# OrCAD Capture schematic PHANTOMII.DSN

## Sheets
1 PhantomII System: size C; title: Phantom ROV: System
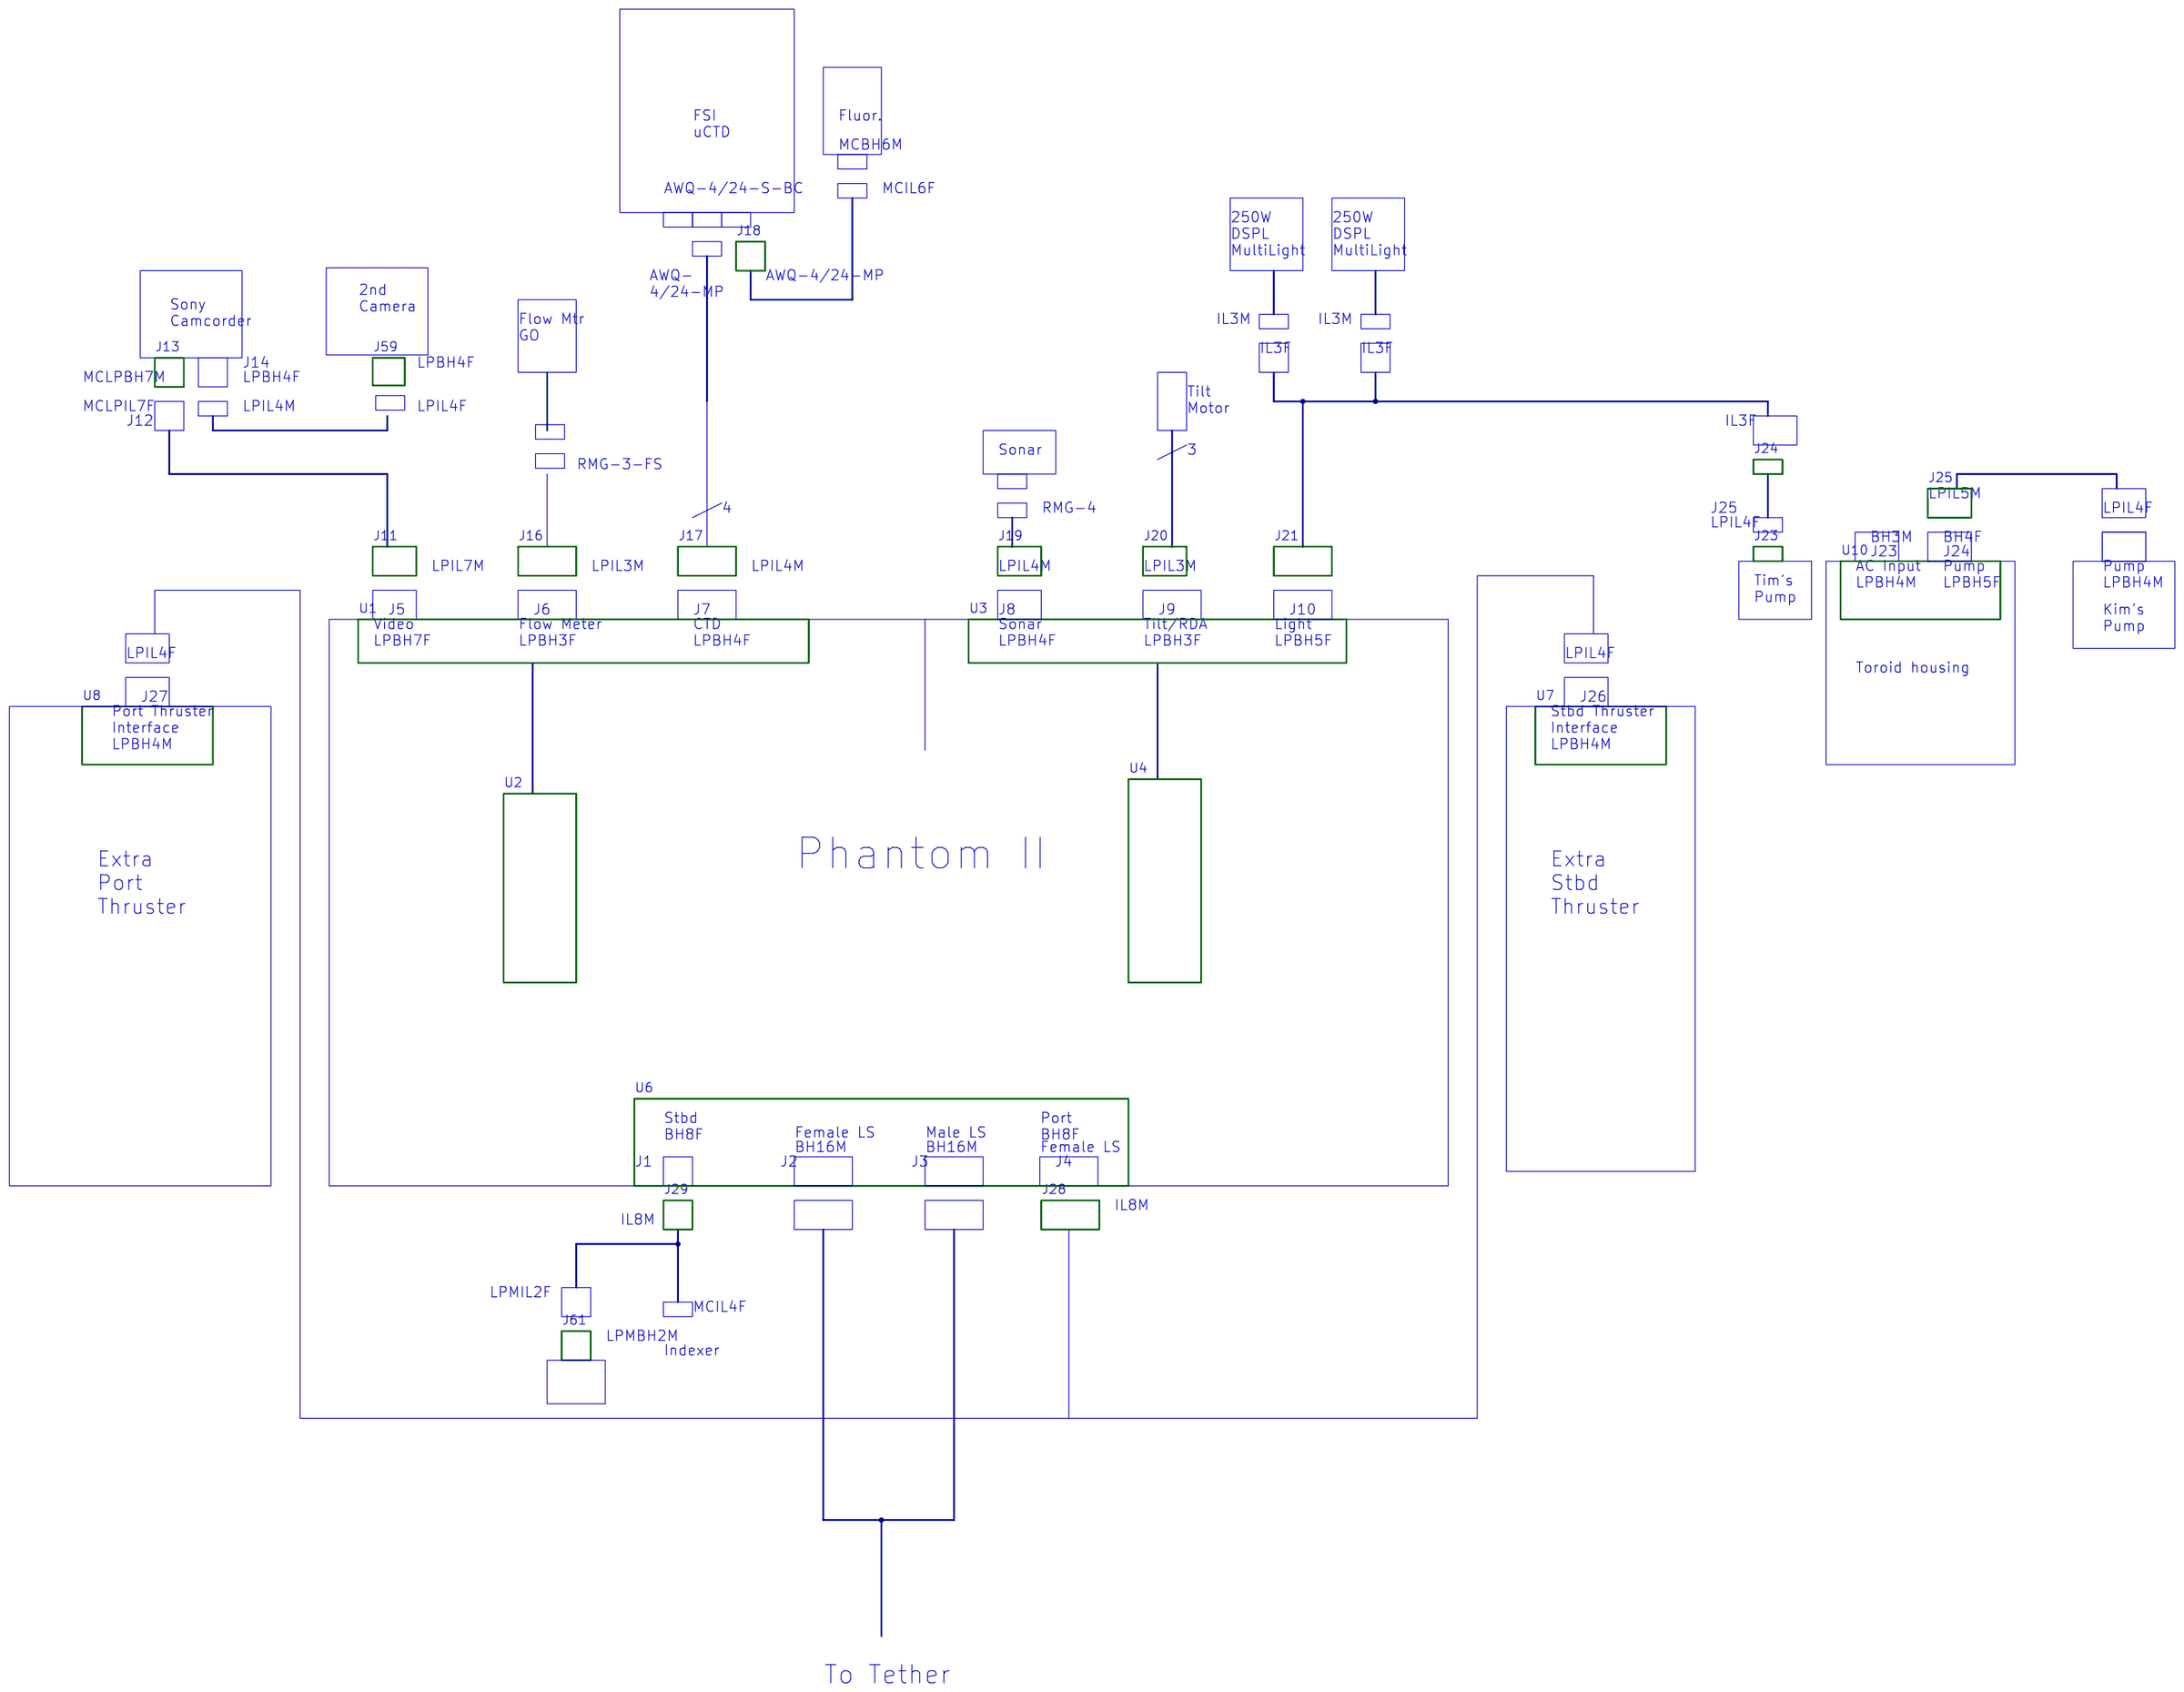
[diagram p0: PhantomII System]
2 J28: size A; title: J28: Phantom Spare Thrusters Cable; block J28
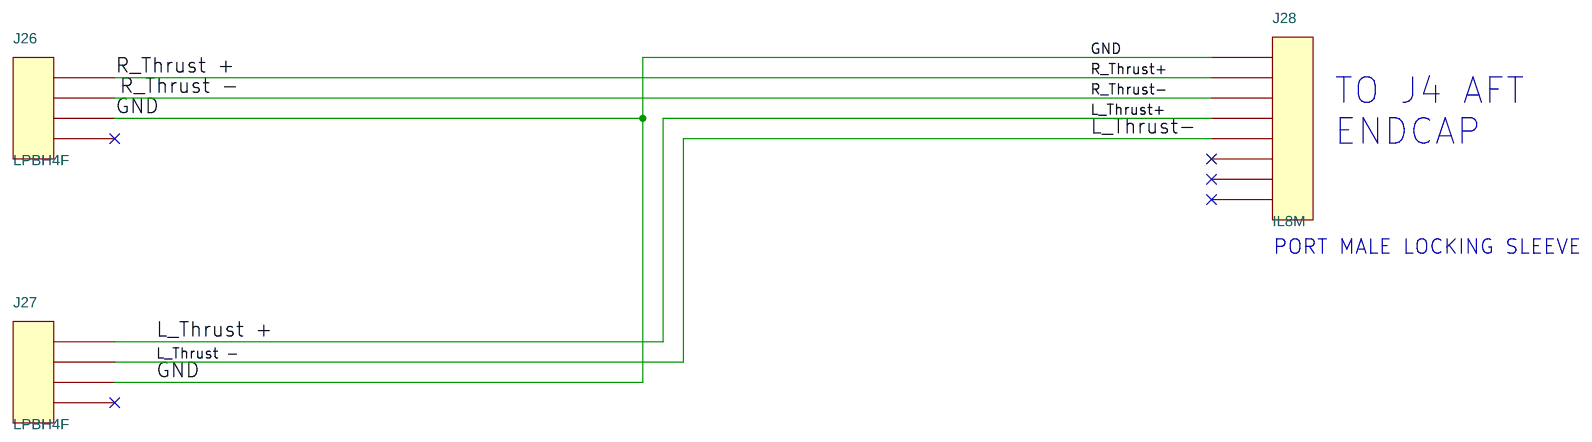
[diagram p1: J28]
3 J24: size A; title: J24: Tim's Pump Cable; block J24
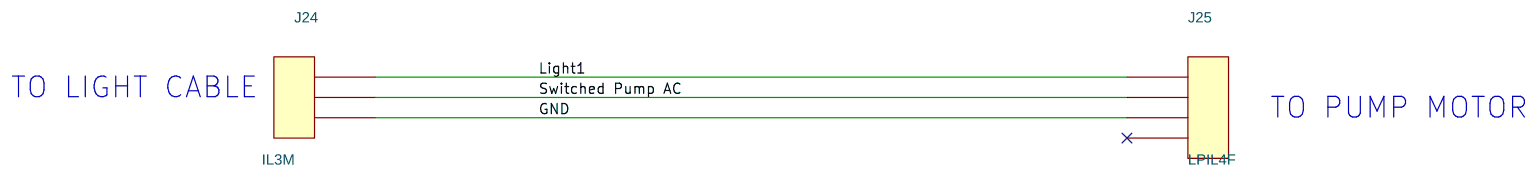
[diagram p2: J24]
4 J25: size A; title: J25: Phantom Pump Cable; block J25
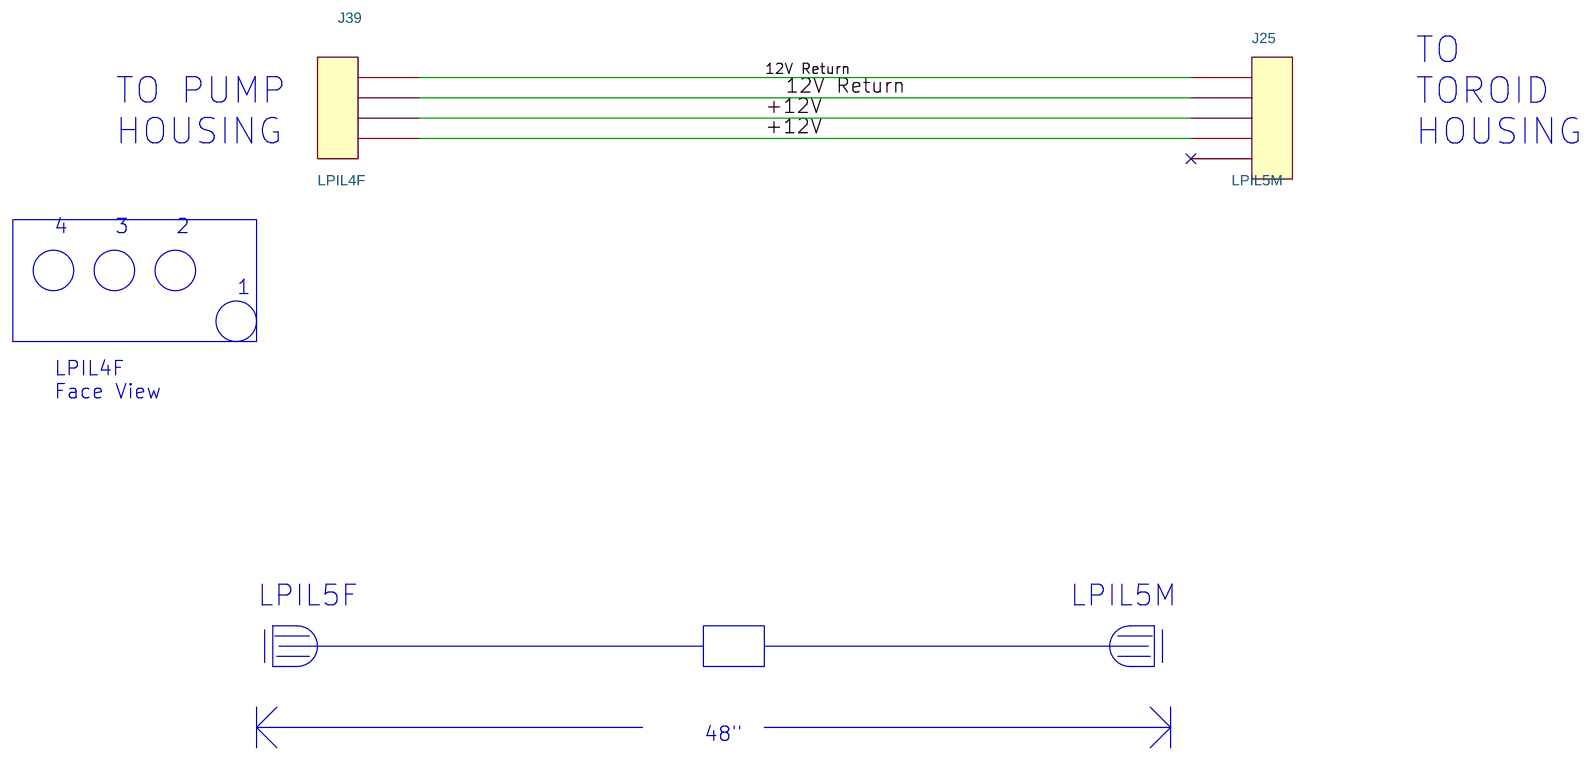
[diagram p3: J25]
5 J29: size A; title: J29:Indexer Cable; block J29
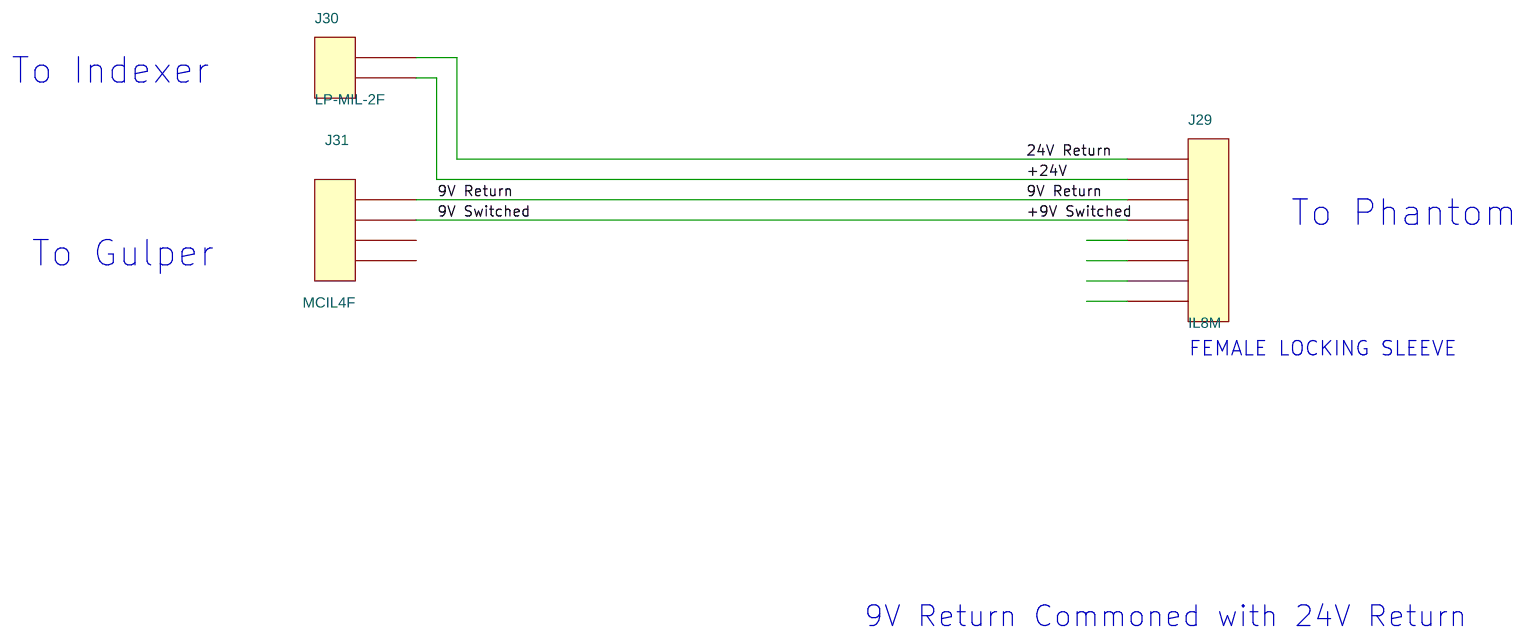
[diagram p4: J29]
6 J11: size A; title: Phantom: J11 Video Cable; block J11
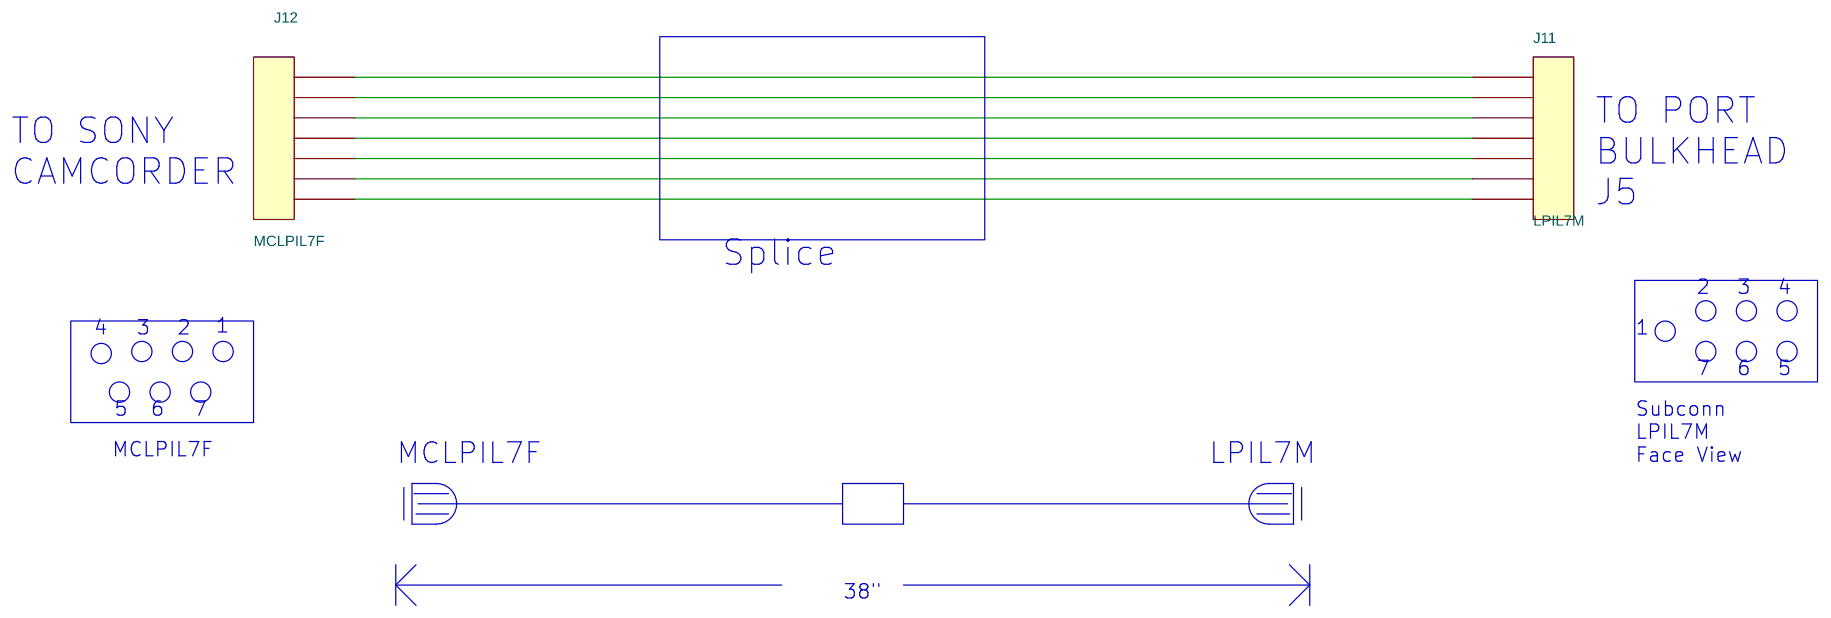
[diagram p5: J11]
7 J13: size B; title: J13: Camcorder Housing Internal Wiring; rev: 1.1.0; block J13
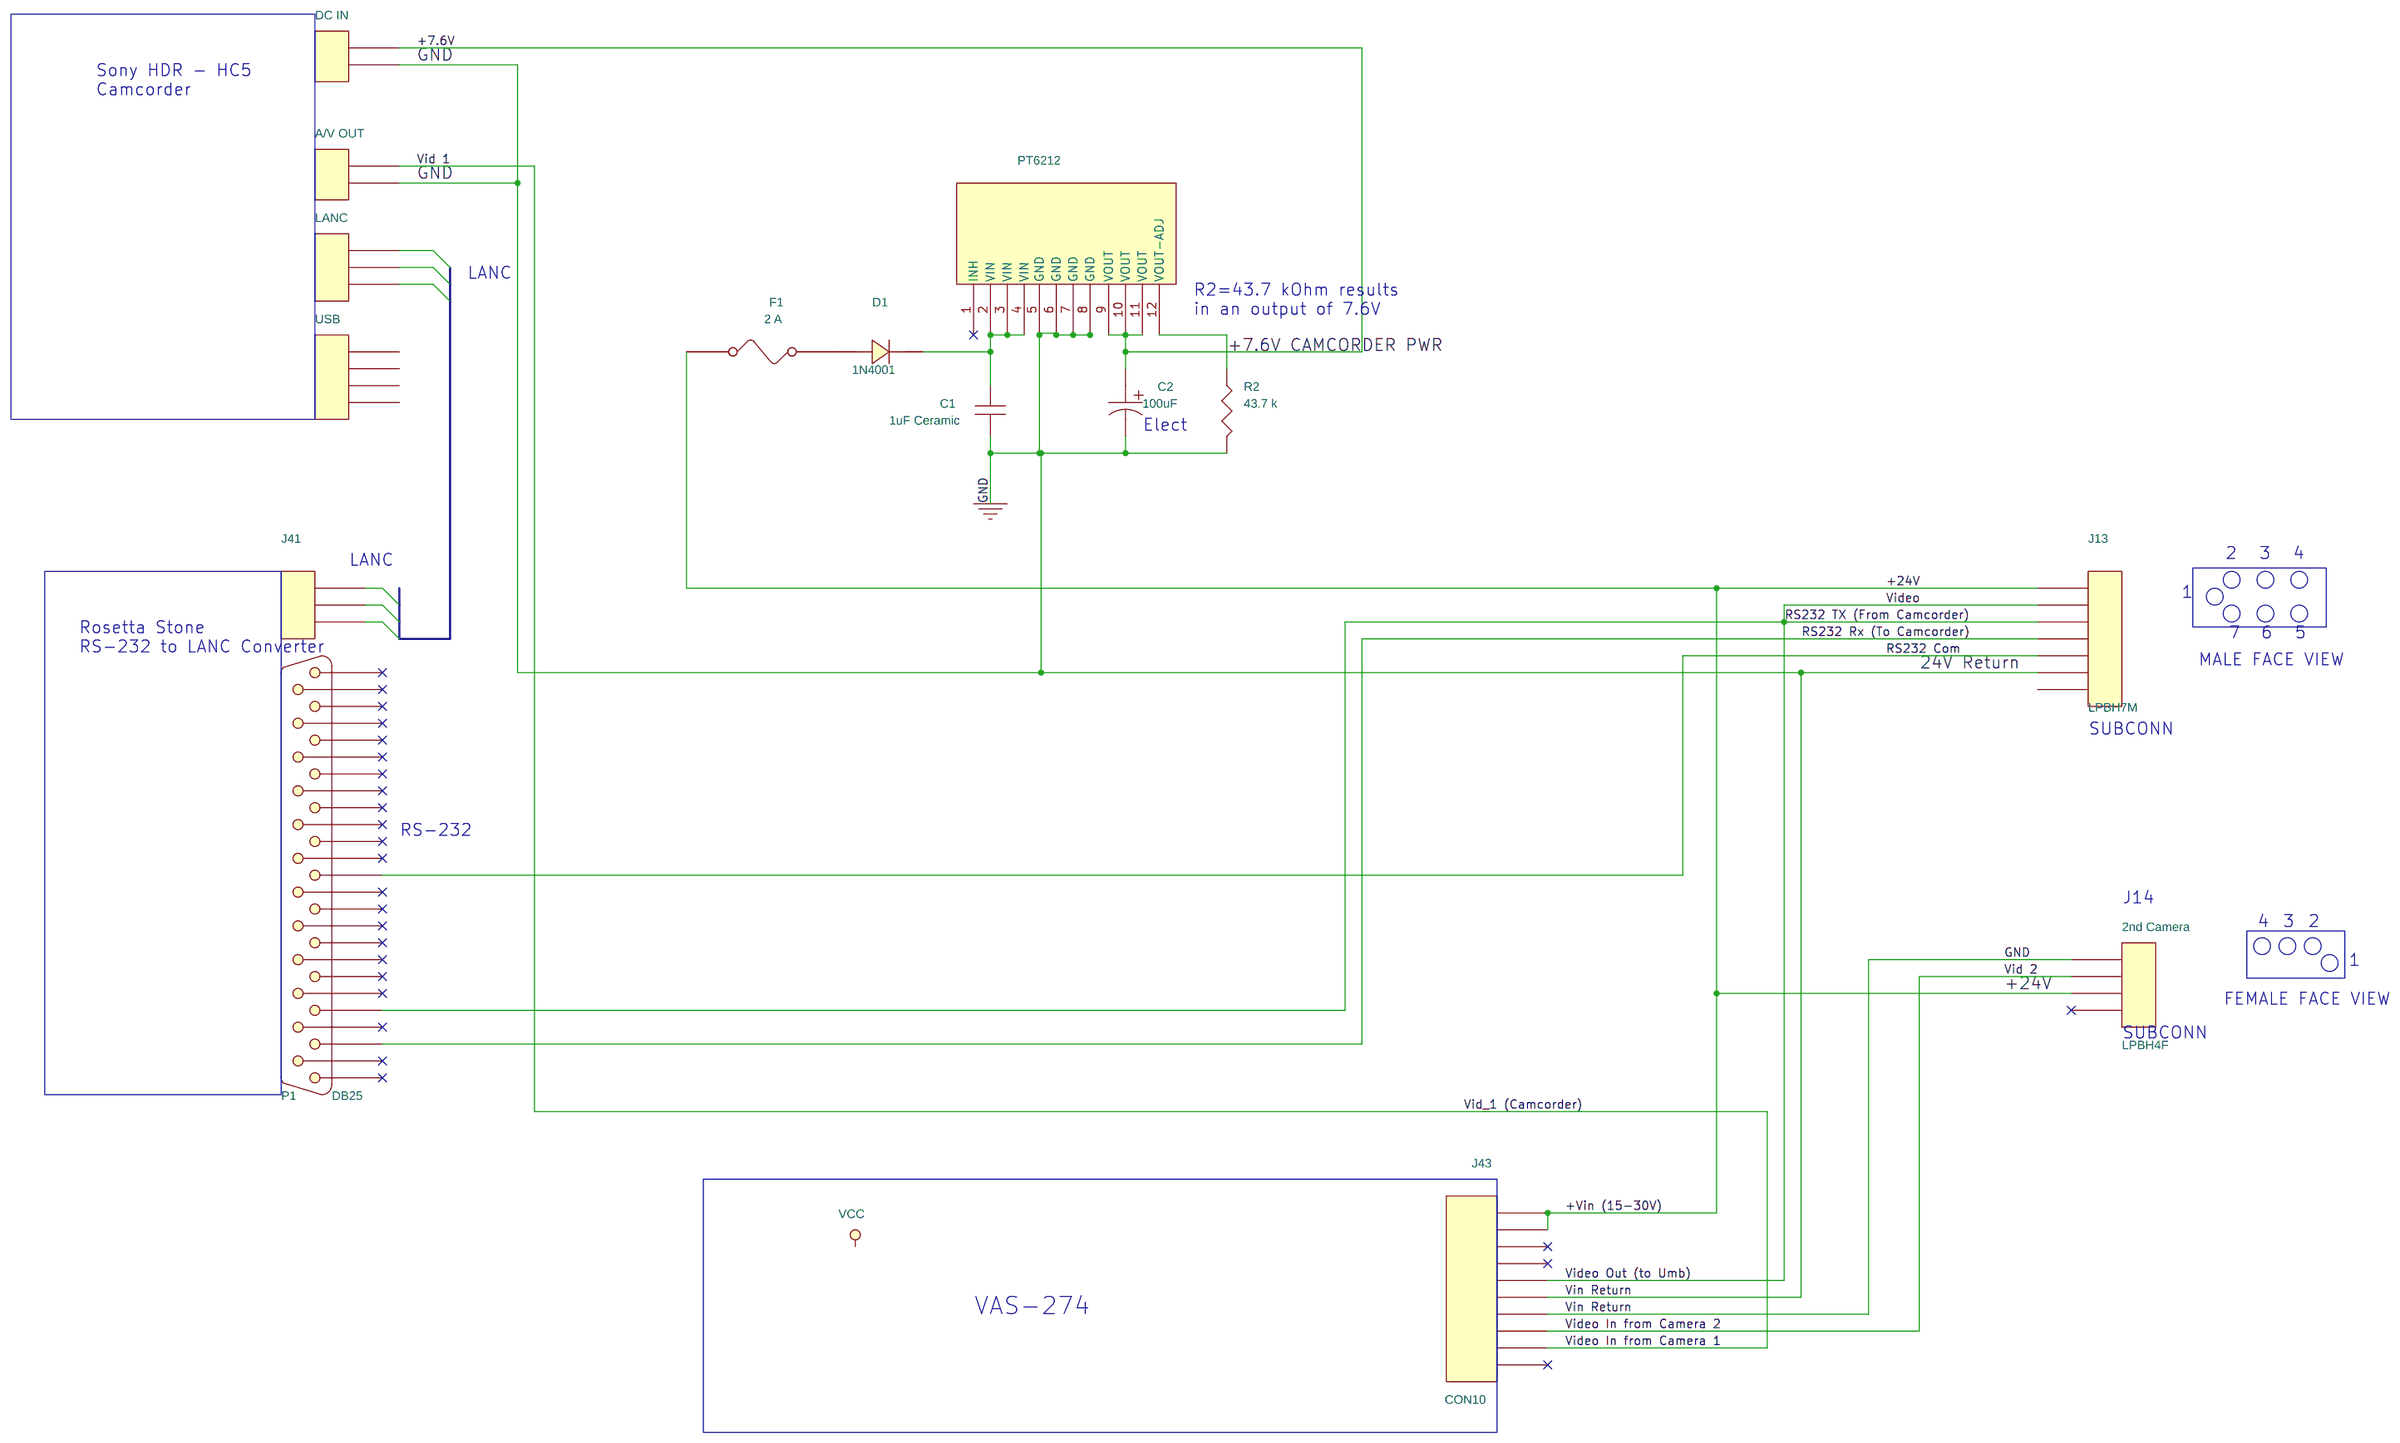
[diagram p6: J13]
8 J15: title: J15: SIT Camera Wiring
9 J21: size A; title: J21: Lights and Pump Cable; block J21
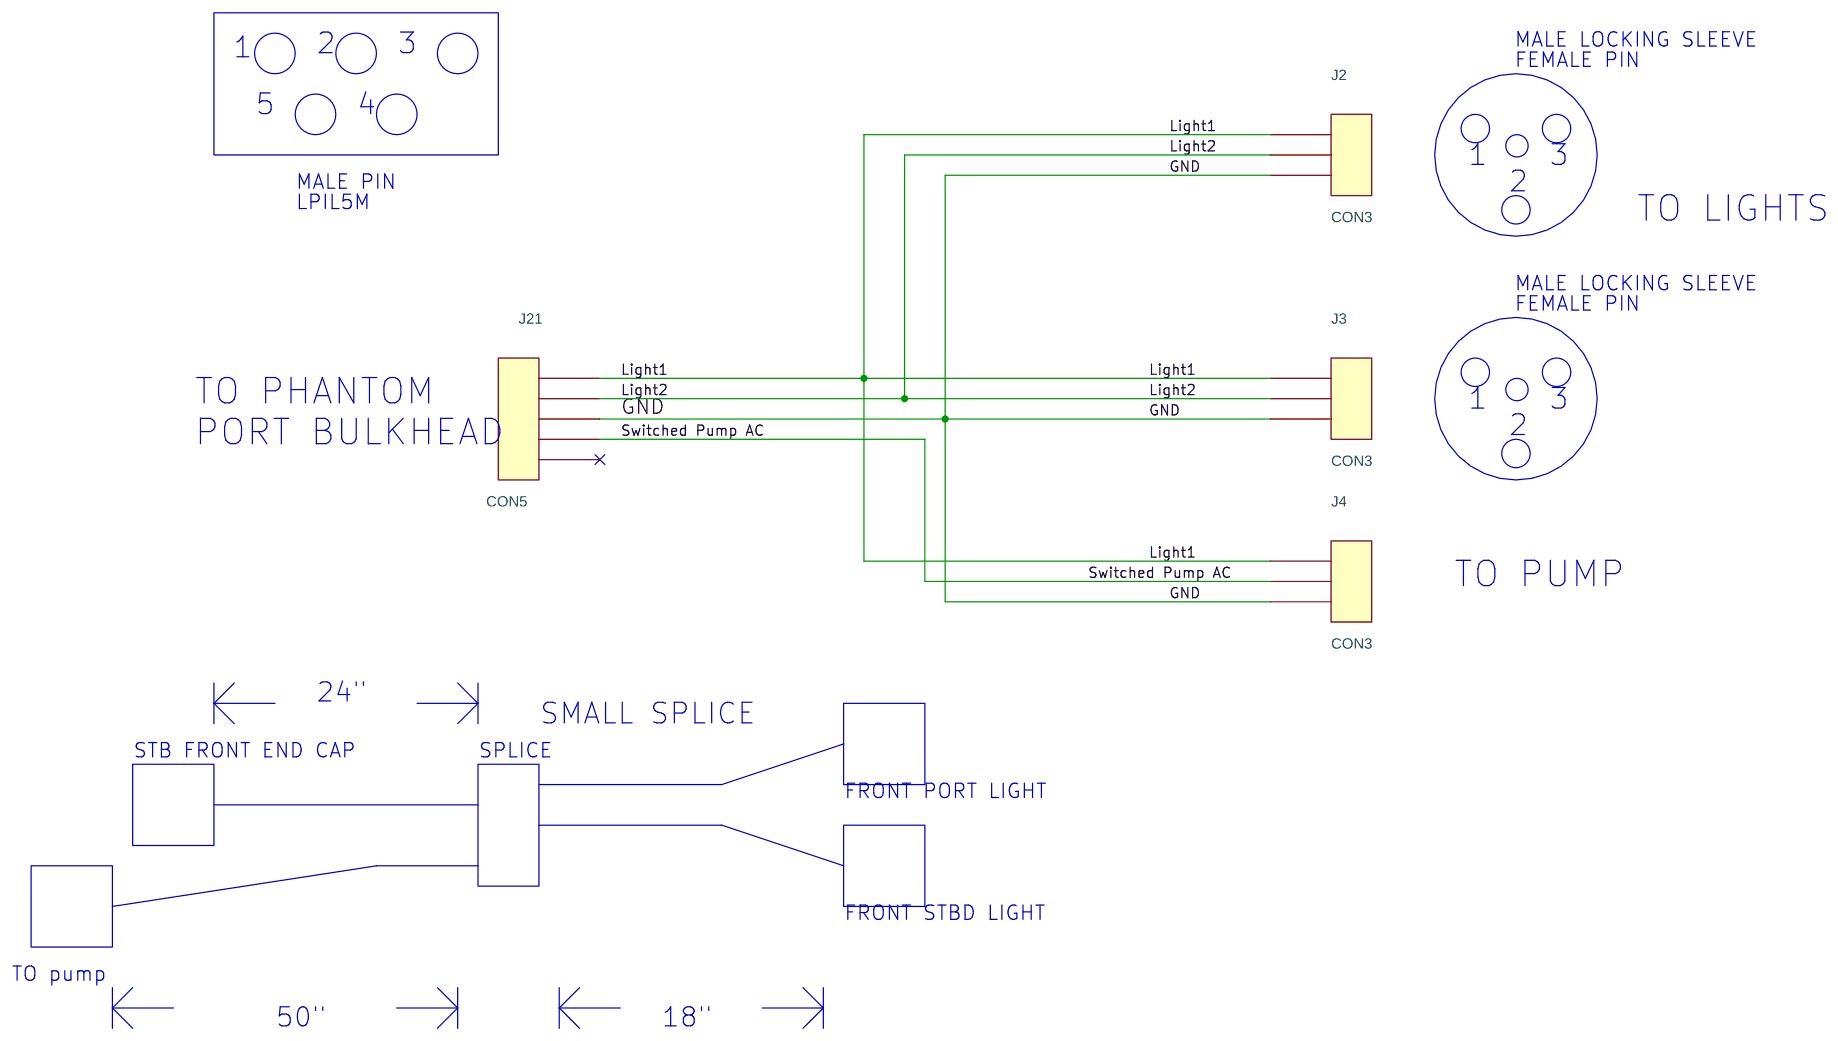
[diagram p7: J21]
10 J19: size A; title: Phantom II: J19 Sonar Cable; block J19
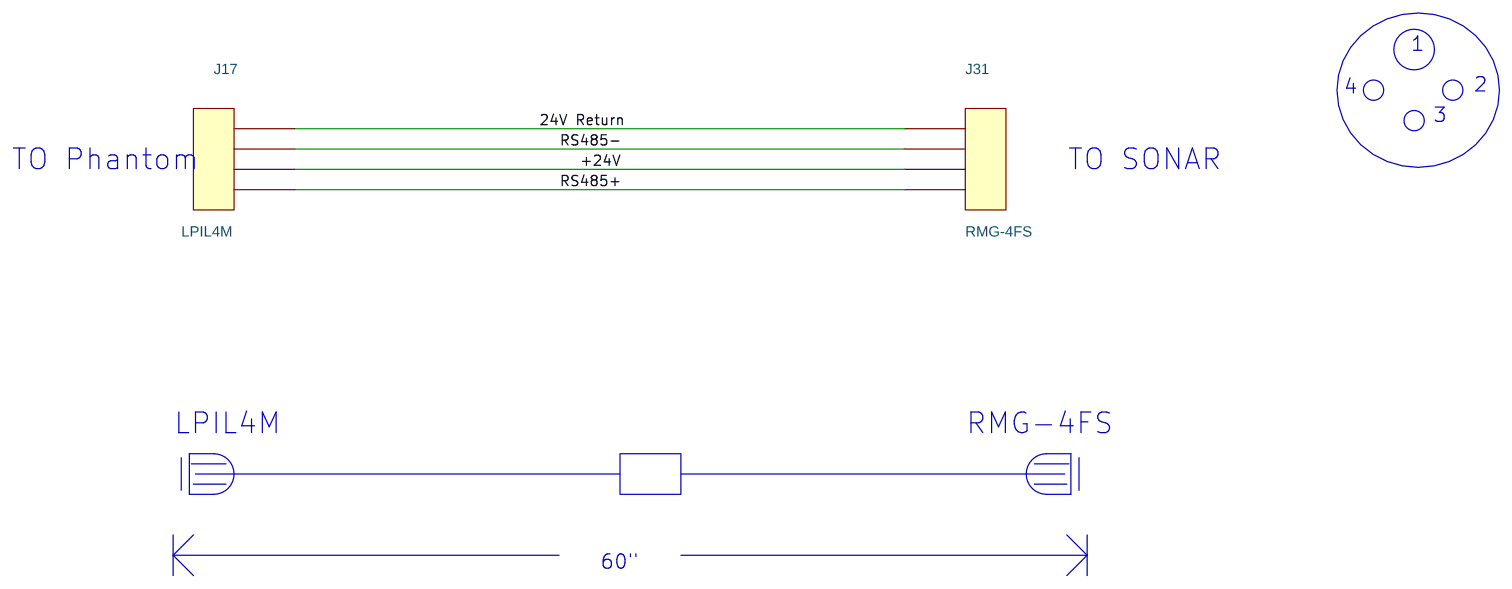
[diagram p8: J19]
11 J18: size A; title: J18: Phantom Fluorometer Cable; block J18
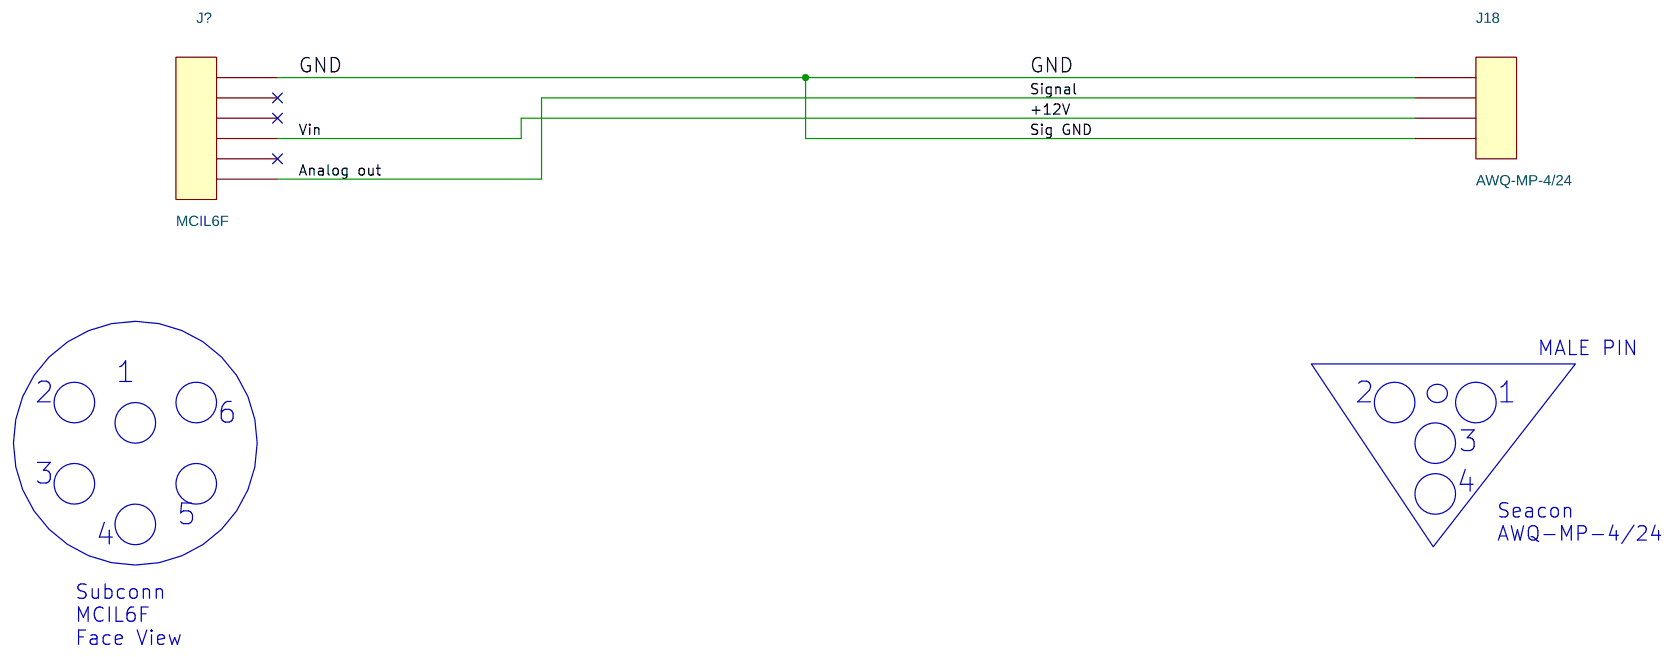
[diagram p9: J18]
12 J23: size A; title: J23: Tim's Pump Motor; block J23
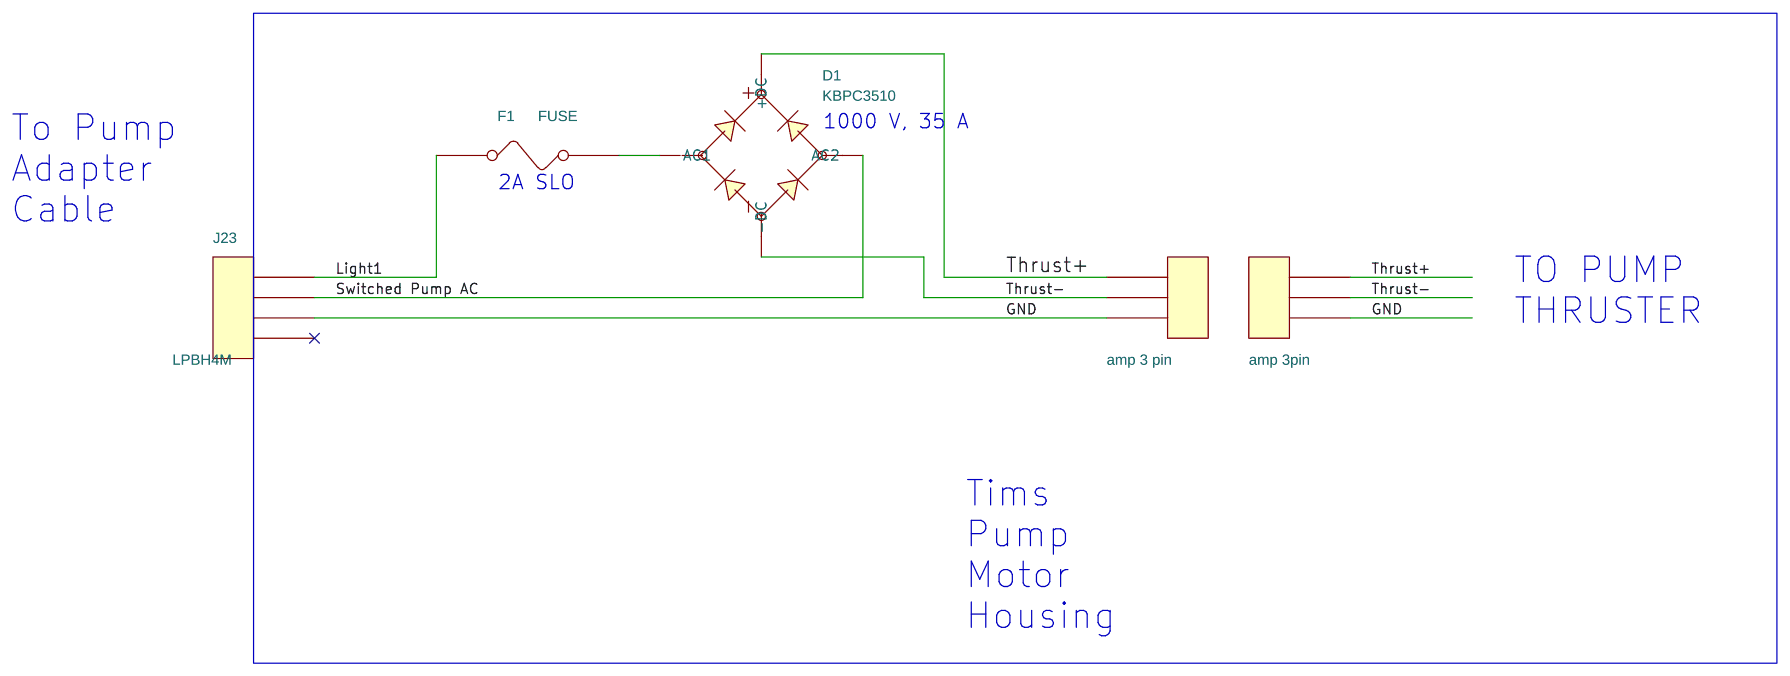
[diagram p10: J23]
13 J20: size A; title: PORT_FRONT_CABLE_HARNESS; block J20
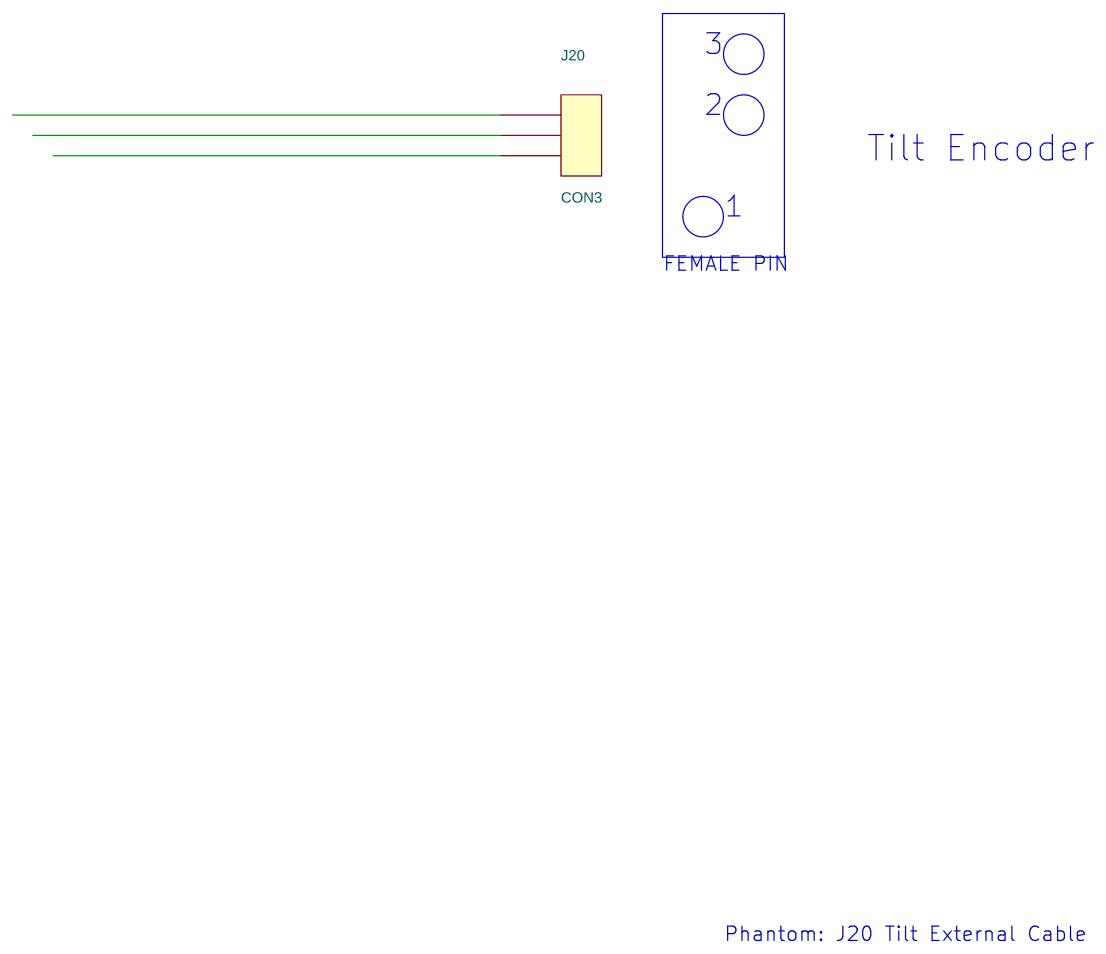
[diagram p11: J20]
14 J17: size A; title: J17: Phantom CTD cable; block J17
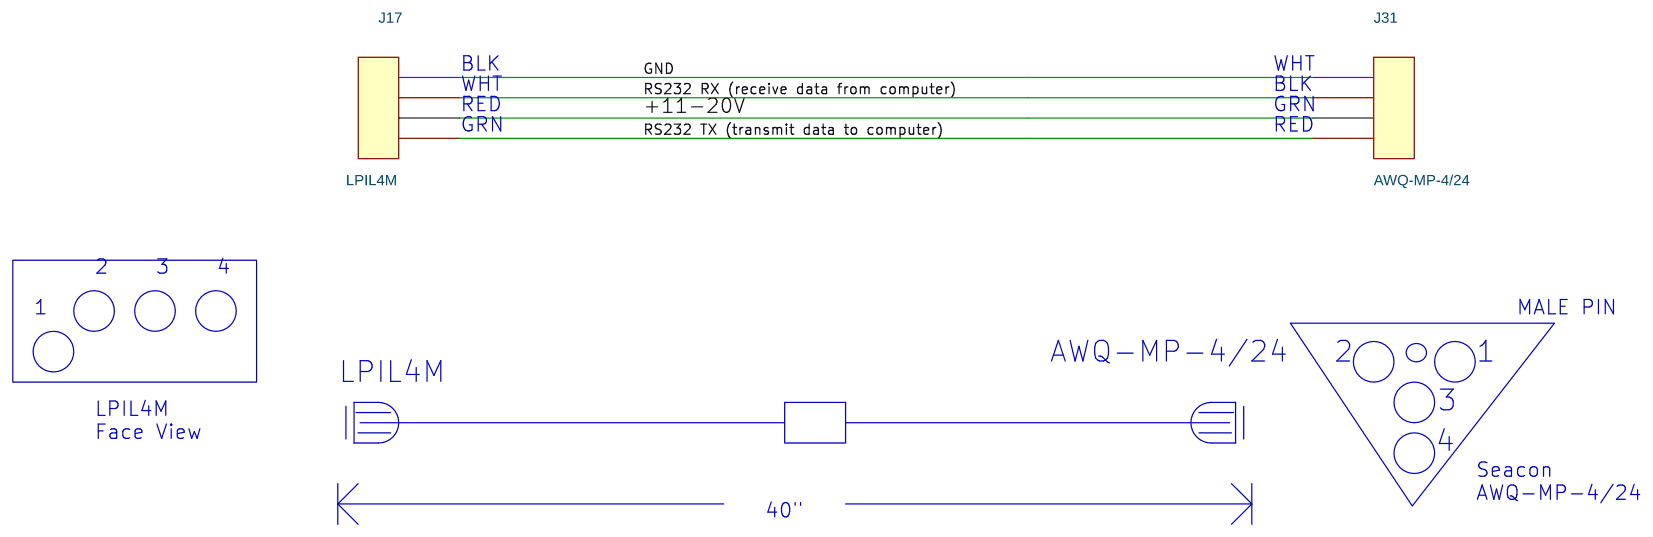
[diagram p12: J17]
15 J16: size A; title: J16: Phantom Flow Meter Cable; block J16
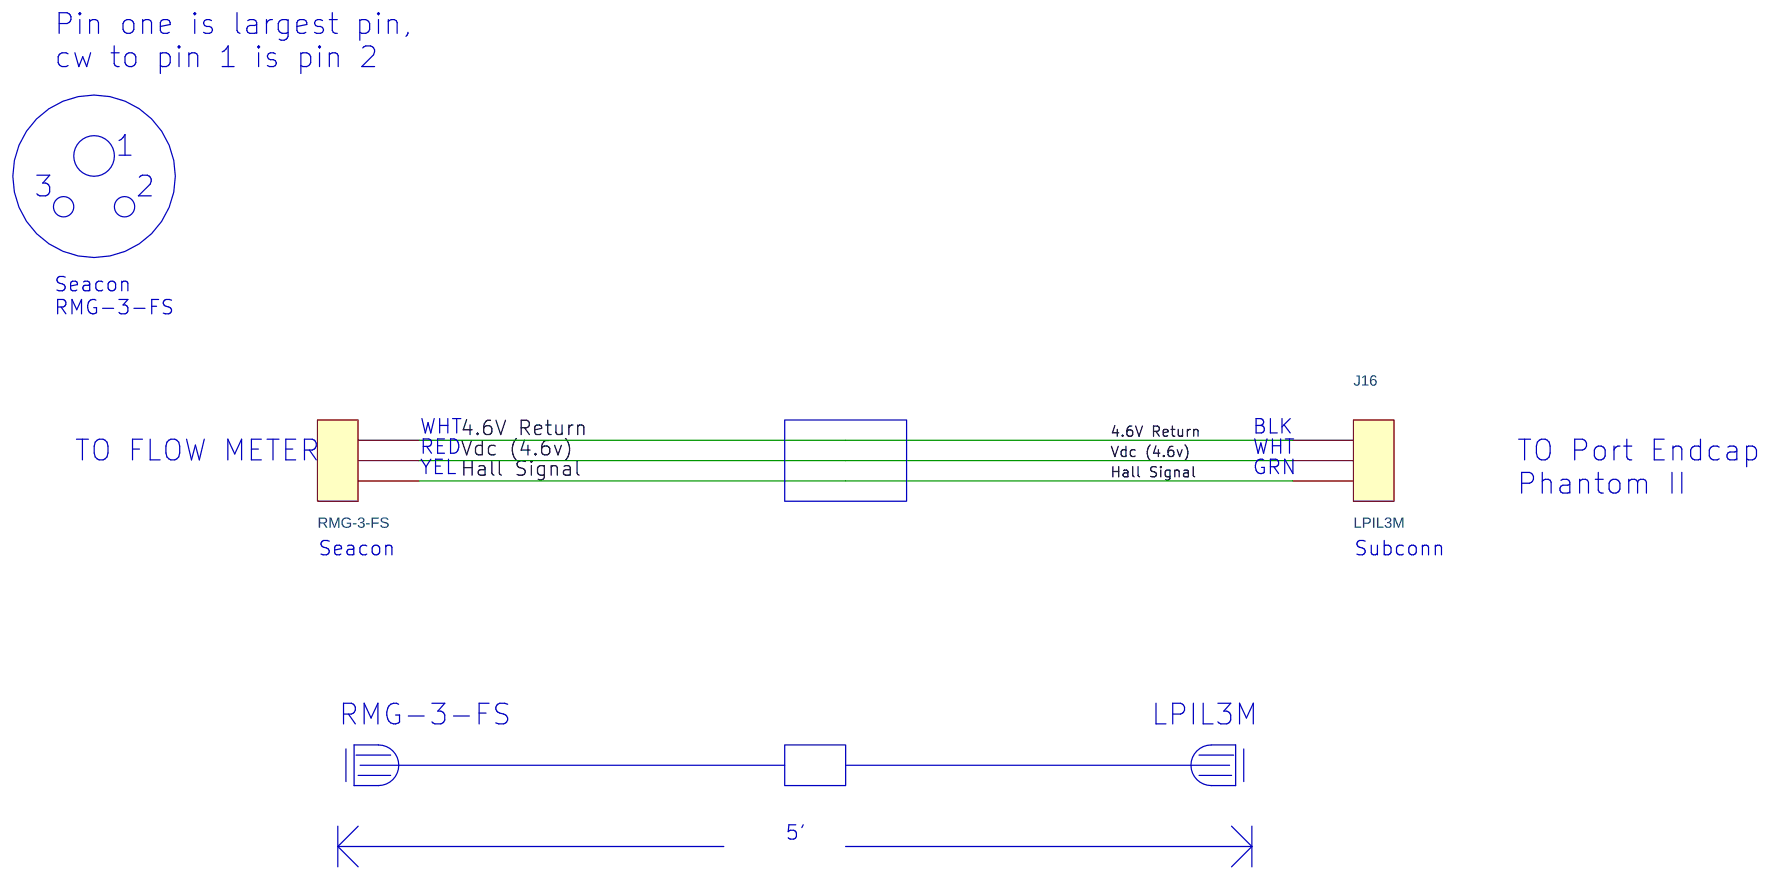
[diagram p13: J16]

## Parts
sheet J11
J11  LPIL7M
J12  MCLPIL7F
sheet J13
2nd Camera  LPBH4F
A/V OUT  CON2
C1  1uF Ceramic
C2  100uF
DC IN  CON2
F1#2  2 A
J13  LPBH7M
J41  CON3
LANC  CON3
P1  DB25
PT6212  PT620*
R2  43.7 k
USB  CON4
sheet J16
J16  LPIL3M
J49  RMG-3-FS
sheet J17
J31#2  AWQ-MP-4/24
sheet J18
J18  AWQ-MP-4/24
J?#1  MCIL6F
sheet J19
J17  LPIL4M
J17#2  LPIL4M
J31#3  RMG-4FS
sheet J20
J20  CON3
sheet J21
J2  CON3
J3  CON3
J4  CON3
J21  CON5
sheet J23
D1  KBPC3510
F1  FUSE
J23  LPBH4M
J42  amp 3 pin
J43  amp 3pin
sheet J24
J24  IL3M
J25  LPIL4F
sheet J25
J39  LPIL4F
sheet J28
J26  LPBH4F
J27  LPBH4F
J28  IL8M
sheet J29
J29  IL8M
J30  LP-MIL-2F
J31  MCIL4F

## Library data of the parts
J11-J13 = CON7
2nd Camera J17 J17#2 J18 J23 J25-J27 J31 J31#2 J31#3 J39 USB = CON4
A/V OUT DC IN J30 = CON2
C1 = CAP_NP
C2 = CAP_POL
F1 F1#2 = FUSE
J2-J4 J16 J20 J24 J41-J43 J49 LANC = CON3
P1 = CONNECTOR_DB25
PT6212 = PT620*_4
R2 = R
J?#1 = CON6
J21 = CON5
D1 = BRIDGE
J28 J29 = CON8

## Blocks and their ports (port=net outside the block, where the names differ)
J59 = schematic J15, on sheet PhantomII System: no ports
J29 = schematic J29, on sheet PhantomII System: no ports
J24 = schematic J24, on sheet PhantomII System: no ports
J21 = schematic J21, on sheet PhantomII System: no ports
J28 = schematic J28, on sheet PhantomII System: no ports
U3 = schematic , on sheet PhantomII System: no ports
U2 = schematic , on sheet PhantomII System: no ports
J18 = schematic J18, on sheet PhantomII System: no ports
U7 = schematic , on sheet PhantomII System: no ports
U10 = schematic , on sheet PhantomII System: no ports
J20 = schematic J20, on sheet PhantomII System: no ports
J23 = schematic J23, on sheet PhantomII System: no ports
U8 = schematic , on sheet PhantomII System: no ports
J17 = schematic J17, on sheet PhantomII System: no ports
J19 = schematic J19, on sheet PhantomII System: no ports
J25 = schematic J25, on sheet PhantomII System: no ports
U4 = schematic , on sheet PhantomII System: no ports
J16 = schematic J16, on sheet PhantomII System: no ports
J61 = schematic , on sheet PhantomII System: no ports
U6 = schematic , on sheet PhantomII System: no ports
U1 = schematic , on sheet PhantomII System: no ports
J11 = schematic J11, on sheet PhantomII System: no ports
J13 = schematic J13, on sheet PhantomII System: no ports

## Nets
GND: 2nd Camera.1 A/V OUT.2 C1.2 C2.2 DC IN.2 J13.6 J43.6 J43.7 PT6212.5(GND) PT6212.6(GND) PT6212.7(GND) PT6212.8(GND) R2.2
J13/+7.6V: C2.1 DC IN.1 PT6212.9(VOUT) PT6212.10(VOUT) PT6212.11(VOUT)
J13/+7.6V CAMCORDER PWR: PT6212.12(VOUT-ADJ) R2.1
J13/+24V: 2nd Camera.3 C1.1 D1.2(K) D1.4(+DC) F1#2.1 J13.1 J42.1 J42.2 J43.1 J43.2 PT6212.2(VIN) PT6212.3(VIN) PT6212.4(VIN)
J16/4.6V Return: J16.1 J49.1
J17/GND: J17.1 J31#2.1
J18/+12V: J18.3 J?#1.4
J18/GND: J18.1 J18.4 J?#1.1
J19/24V Return: J17#2.1 J31#3.1
J19/+24V: J17#2.3 J31#3.3
J21/GND: J2.3 J3.3 J4.3 J21.3
J23/GND: J23.3 J42.3 J43.3
J25/12V Return: J24.1 J24.2 J25.1 J25.2 J39.1 J39.2
J25/+12V: J24.3 J25.3 J25.4 J39.3 J39.4
J28/GND: J26.3 J27.3 J28.1
J29/9V Return: J29.3 J31.1
J29/24V Return: J29.1 J30.1
J29/+9V Switched: J29.4 J31.2
J29/+24V: J29.2 J30.2
J13/RS232 Com: J13.5 P1.7
J13/RS232 Rx (To Camcorder): J13.4 P1.2
J13/RS232 TX (From Camcorder): J13.3 P1.3
J13/Vid 1: A/V OUT.1 J43.9
J13/Vid 2: 2nd Camera.2 J43.8
J13/Video: J13.2 J43.5
J16/Hall Signal: J16.3 J49.3
J16/Vdc (4.6v): J16.2 J49.2
J17/+11-20V: J17.3 J31#2.3
J17/RS232 RX (receive data from computer): J17.2 J31#2.2
J17/RS232 TX (transmit data to computer): J17.4 J31#2.4
J18/Analog out: J18.2 J?#1.6
J19/RS485+: J17#2.4 J31#3.4
J19/RS485-: J17#2.2 J31#3.2
J21/Light1: J2.1 J3.1 J4.1 J21.1
J21/Light2: J2.2 J3.2 J21.2
J21/Switched Pump AC: J4.2 J21.4
J23/Light1: F1.1 J23.1
J23/Switched Pump AC: D1.3(AC2) J23.2
J28/L_Thrust +: J27.1 J28.4
J28/L_Thrust -: J27.2 J28.5
J28/R_Thrust +: J26.1 J28.2
J28/R_Thrust -: J26.2 J28.3
J11/N108191: J11.1 J12.1
J11/N108193: J11.2 J12.2
J11/N108195: J11.3 J12.3
J11/N108197: J11.4 J12.4
J11/N108199: J11.5 J12.5
J11/N108201: J11.6 J12.6
J11/N108203: J11.7 J12.7
J23/N75737: D1.1(A) F1.2 F1#2.2

Not connected (* = marked no-connect by the designer): 2nd Camera 4*; J13 7; J20 1 2 3; J21 5*; J23 4*; J25 5*; J26 4*; J27 4*; J28 6* 7* 8*; J29 5 6 7 8; J31 3 4; J41 1 2 3; J43 4* 10*; J?#1 2* 3* 5*; LANC 1 2 3; P1 1* 4* 5* 6* 8* 9* 10* 11* 12* 13* 14* 15* 16* 17* 18* 19* 20* 21* 22* 23* 24* 25*; PT6212 1(INH)*; USB 1 2 3 4

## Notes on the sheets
sheet 1
- FSI
  uCTD
- Fluor.
- MCBH6M
- AWQ-4/24-S-BC
- MCIL6F
- 250W
  DSPL
  MultiLight
- 250W
  DSPL
  MultiLight
- AWQ-
  4/24-MP
- AWQ-4/24-MP
- 2nd
  Camera
- Sony
  Camcorder
- Flow Mtr
  GO
- IL3M
- IL3M
- J14
- LPBH4F
- IL3F
- IL3F
- MCLPBH7M
- LPBH4F
- Tilt
  Motor
- MCLPIL7F
- LPIL4M
- LPIL4F
- J12
- IL3F
- Sonar
- 3
- RMG-3-FS
- LPIL5M
- 4
- RMG-4
- J25
- LPIL4F
- LPIL4F
- BH3M
- J23
- BH4F
- J24
- LPIL7M
- LPIL3M
- LPIL4M
- LPIL4M
- LPIL3M
- AC Input
  LPBH4M
- Pump
  LPBH5F
- Pump
  LPBH4M
- Tim's
  Pump
- J5
- J6
- J7
- J8
- J9
- J10
- Kim's
  Pump
- Video
  LPBH7F
- Flow Meter
  LPBH3F
- CTD
  LPBH4F
- Sonar
  LPBH4F
- Tilt/RDA
  LPBH3F
- Light
  LPBH5F
- LPIL4F
- LPIL4F
- Toroid housing
- J27
- J26
- Port Thruster
  Interface
  LPBH4M
- Stbd Thruster
  Interface
  LPBH4M
- Phantom II
- Extra
  Port
  Thruster
- Extra
  Stbd
  Thruster
- Stbd
  BH8F
- Port
  BH8F
- Female LS
- Male LS
- BH16M
- BH16M
- Female LS
- J1
- J2
- J3
- J4
- IL8M
- IL8M
- LPMIL2F
- MCIL4F
- LPMBH2M
- Indexer
- To Tether
sheet 2
- TO J4 AFT
  ENDCAP
- PORT MALE LOCKING SLEEVE
sheet 3
- TO LIGHT CABLE
- TO PUMP MOTOR
sheet 4
- TO
  TOROID
  HOUSING
- TO PUMP
  HOUSING
- 4
- 3
- 2
- 1
- LPIL4F
  Face View
- LPIL5F
- LPIL5M
- 48"
sheet 5
- To Indexer
- To Phantom
- To Gulper
- FEMALE LOCKING SLEEVE
- 9V Return Commoned with 24V Return
sheet 6
- TO PORT
  BULKHEAD
  J5
- TO SONY
  CAMCORDER
- Splice
- 2
- 3
- 4
- 4
- 3
- 2
- 1
- 1
- 7
- 6
- 5
- 5
- 6
- 7
- Subconn
  LPIL7M
  Face View
- MCLPIL7F
- MCLPIL7F
- LPIL7M
- 38"
sheet 7
- Sony HDR - HC5
  Camcorder
- LANC
- R2=43.7 kOhm results
  in an output of 7.6V
- Elect
- 2
- 3
- 4
- LANC
- 1
- Rosetta Stone
  RS-232 to LANC Converter
- 7
- 6
- 5
- MALE FACE VIEW
- SUBCONN
- RS-232
- J14
- 4
- 3
- 2
- 1
- FEMALE FACE VIEW
- SUBCONN
- VAS-274
sheet 9
- 1
- 2
- 3
- MALE LOCKING SLEEVE
- FEMALE PIN
- 5
- 4
- 1
- 3
- MALE PIN
- 2
- LPIL5M
- TO LIGHTS
- MALE LOCKING SLEEVE
- FEMALE PIN
- TO PHANTOM
  PORT BULKHEAD
- 1
- 3
- 2
- TO PUMP
- 24"
- SMALL SPLICE
- STB FRONT END CAP
- SPLICE
- FRONT PORT LIGHT
- FRONT STBD LIGHT
- TO pump
- 50"
- 18"
sheet 10
- 1
- 4
- 2
- 3
- TO Phantom
- TO SONAR
- LPIL4M
- RMG-4FS
- 60"
sheet 11
- MALE PIN
- 2
- 1
- 2
- 1
- 6
- 3
- 3
- 4
- 5
- Seacon
  AWQ-MP-4/24
- 4
- Subconn
  MCIL6F
  Face View
sheet 12
- To Pump
  Adapter
  Cable
- 1000 V, 35 A
- 2A SLO
- TO PUMP
  THRUSTER
- Tims
  Pump
  Motor
  Housing
sheet 13
- 3
- 2
- Tilt Encoder
- 1
- FEMALE PIN
- Phantom: J20 Tilt External Cable
sheet 14
- BLK
- WHT
- WHT
- BLK
- GRN
- RED
- GRN
- RED
- 2
- 3
- 4
- 1
- MALE PIN
- AWQ-MP-4/24
- 2
- 1
- LPIL4M
- LPIL4M
  Face View
- 3
- 4
- Seacon
  AWQ-MP-4/24
- 40"
sheet 15
- Pin one is largest pin,
  cw to pin 1 is pin 2
- 1
- 3
- 2
- Seacon
  RMG-3-FS
- WHT
- BLK
- TO FLOW METER
- RED
- WHT
- TO Port Endcap
  Phantom II
- YEL
- GRN
- Seacon
- Subconn
- RMG-3-FS
- LPIL3M
- 5'
